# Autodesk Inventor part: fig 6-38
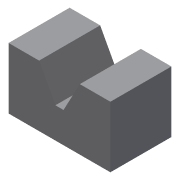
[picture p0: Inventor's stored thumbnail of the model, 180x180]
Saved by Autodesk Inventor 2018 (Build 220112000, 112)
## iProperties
Created: 2005-12
Part Number: fig 6-38
Document SubType Name: Modeling
Designer: CADCIM
Density: 1 g/cm^3
Material: Generic
Appearance: Default
Author: CADCIM
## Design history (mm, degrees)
sketch "Sketch1"
  geometry: L1 (10, 15)-(25, 15); L2 (25, 15)-(25, -15); L3 (25, -15)-(-25, -15); L4 (-25, -15)-(-25, 15); L5 (-25, 15)-(-10, 15); L6 (-10, 15)-(-2, 0); L7 (-2, 0)-(2, 0); L8 (2, 0)-(10, 15); 1 further point
  constraints: 16 end point, 3 equal length, 3 parallel, 1 collinear, 1 horizontal, 1 perpendicular, 1 other
  dimensions: "d0" = 50 distance of L2.end L3.end; "d1" = 25 distance from line of point (0, 0) L2; "d2" = 30 distance of L1.end L2.end; "d3" = 15 distance of L1.start L1.end; "d4" = 15 distance between parallel lines of L1 L7; "d5" = 4 distance of L6.end L7.end; "d6" = 15 distance from line of point (0, 0) L3
extrude "Extrusion1" new body sketch "Sketch1" stored distance "d7" = 30; taper "d8" = 0 deg
body "Solid1"
